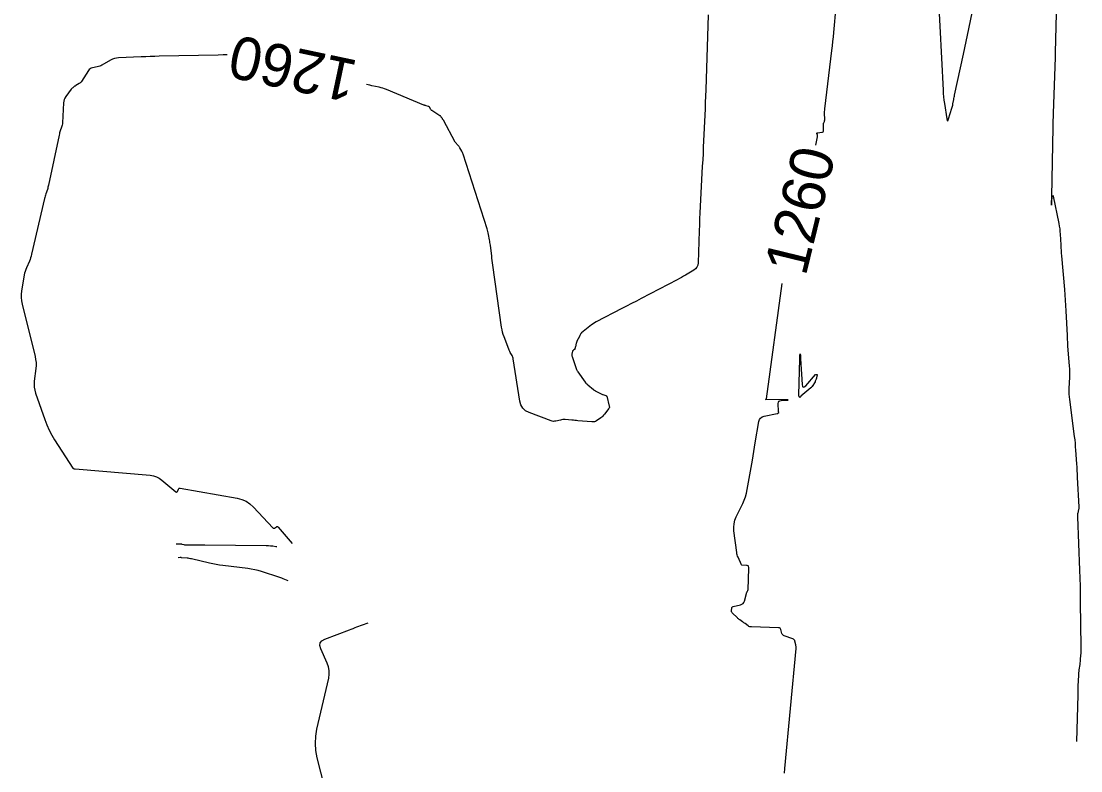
# Model space of a CAD drawing. Extents: x 658976 to 668726, y 639543 to 647196.
# Drawn here: x 660588.2 to 660736.7, y 642362.1 to 642467.2 of the extents above; entities that cross this region are included whole.
import ezdxf

# ---------------------------------------------------------------- set-up
doc = ezdxf.new("R2010")
doc.units = 0
doc.layers.add('Ex_Contour Labels', color=7, linetype='Continuous')
doc.layers.add('Ex_Major Contours', color=7, linetype='Continuous')

msp = doc.modelspace()

# ---------------------------------------------------------------- linework, layer by layer
at = {"layer": 'Ex_Major Contours'}
for points in [[(660733.36, 642471.99), (660733.11, 642462.8), (660733.11, 642462.62), (660733.1, 642462.44), (660733.1, 642462.27), (660733.09, 642462.09), (660732.81, 642454.31), (660732.8, 642453.8), (660732.78, 642453.29), (660732.77, 642452.78), (660732.76, 642452.27), (660732.59, 642442.62), (660732.58, 642442.53), (660732.58, 642442.45), (660732.58, 642442.36), (660732.58, 642442.27), (660732.57, 642441.44), (660732.57, 642441.41), (660732.57, 642441.4), (660732.57, 642441.41), (660732.57, 642441.44), (660732.59, 642441.75), (660732.59, 642441.77), (660732.59, 642441.8), (660732.59, 642441.83), (660732.59, 642441.86), (660732.6, 642441.98), (660732.61, 642442.01), (660732.61, 642442.04), (660732.61, 642442.07), (660732.62, 642442.1), (660732.73, 642442.64), (660732.76, 642442.72), (660732.78, 642442.74), (660732.8, 642442.72), (660732.82, 642442.64), (660733.61, 642438.84), (660733.68, 642438.47), (660733.74, 642438.09), (660733.78, 642437.72), (660733.81, 642437.34), (660733.88, 642435.81), (660733.9, 642435.43), (660733.93, 642435.05), (660733.96, 642434.67), (660733.99, 642434.29), (660734.41, 642429.55), (660734.47, 642428.81), (660734.52, 642428.06), (660734.57, 642427.32), (660734.61, 642426.58), (660734.77, 642423.13), (660734.79, 642422.62), (660734.82, 642422.11), (660734.85, 642421.6), (660734.89, 642421.09), (660735.07, 642418.82), (660735.09, 642418.43), (660735.11, 642418.04), (660735.11, 642417.65), (660735.09, 642417.25), (660735.02, 642415.68), (660735.01, 642415.29), (660735.02, 642414.9), (660735.05, 642414.51), (660735.09, 642414.12), (660735.78, 642408.96), (660735.84, 642408.48), (660735.89, 642408), (660735.93, 642407.52), (660735.97, 642407.04), (660736.1, 642405.12), (660736.13, 642404.64), (660736.16, 642404.16), (660736.19, 642403.67), (660736.21, 642403.19), (660736.41, 642399.07), (660736.42, 642398.98), (660736.41, 642398.88), (660736.4, 642398.79), (660736.38, 642398.69), (660736.26, 642398.21), (660736.25, 642398.17), (660736.24, 642398.12), (660736.23, 642398.08), (660736.23, 642398.03), (660736.24, 642397.84), (660736.24, 642397.8), (660736.24, 642397.75), (660736.24, 642397.7), (660736.24, 642397.66), (660736.53, 642390.18), (660736.56, 642389.06), (660736.6, 642387.95), (660736.62, 642386.83), (660736.63, 642385.72), (660736.7, 642379.44), (660736.7, 642379.23), (660736.69, 642379.03), (660736.69, 642378.82), (660736.68, 642378.61), (660736.63, 642377.77), (660736.62, 642377.57), (660736.6, 642377.38), (660736.58, 642377.18), (660736.55, 642376.99), (660736.44, 642376.21), (660736.41, 642376.01), (660736.39, 642375.82), (660736.38, 642375.62), (660736.37, 642375.43), (660736.3, 642373.97), (660736.29, 642373.66), (660736.28, 642373.35), (660736.27, 642373.04), (660736.26, 642372.73), (660736.11, 642366.16)], [(660716.72, 642471.05), (660717.39, 642457.52), (660717.42, 642457.06), (660717.46, 642456.59), (660717.51, 642456.13), (660717.57, 642455.67), (660717.9, 642453.52), (660717.95, 642453.29), (660718.01, 642453.21), (660718.09, 642453.28), (660718.17, 642453.5), (660718.62, 642454.98), (660718.66, 642455.13), (660718.7, 642455.29), (660718.74, 642455.44), (660718.77, 642455.59), (660718.88, 642456.21), (660718.91, 642456.36), (660718.94, 642456.52), (660718.97, 642456.67), (660719, 642456.83), (660720.24, 642462.59), (660720.43, 642463.47), (660720.62, 642464.35), (660720.81, 642465.23), (660720.99, 642466.11), (660722.04, 642471.11)], [(660699.55, 642449.82), (660699.77, 642450.96), (660699.78, 642451.02), (660699.78, 642451.08), (660699.78, 642451.14), (660699.77, 642451.2), (660699.71, 642451.43), (660699.71, 642451.49), (660699.72, 642451.52), (660699.76, 642451.55), (660699.81, 642451.56), (660700.39, 642451.62), (660700.49, 642451.64), (660700.57, 642451.69), (660700.61, 642451.77), (660700.62, 642451.88), (660700.61, 642452.71), (660700.61, 642452.76), (660700.62, 642452.82), (660700.64, 642452.88), (660700.66, 642452.93), (660700.76, 642453.14), (660700.78, 642453.19), (660700.79, 642453.25), (660700.8, 642453.3), (660700.8, 642453.36), (660700.77, 642454.33), (660700.77, 642454.38), (660700.77, 642454.43), (660700.77, 642454.47), (660700.78, 642454.52), (660700.8, 642454.71), (660700.8, 642454.76), (660700.81, 642454.8), (660700.81, 642454.85), (660700.82, 642454.9), (660701.81, 642463.08), (660701.88, 642463.72), (660701.95, 642464.36), (660702.02, 642465), (660702.08, 642465.63), (660702.42, 642469.26)], [(660684.46, 642468.07), (660684.12, 642457.59), (660684.09, 642456.7), (660684.06, 642455.8), (660684.02, 642454.91), (660683.98, 642454.01), (660683.82, 642450.43), (660683.78, 642449.54), (660683.74, 642448.65), (660683.69, 642447.75), (660683.64, 642446.86), (660683.34, 642441.19), (660683.29, 642440.33), (660683.25, 642439.48), (660683.22, 642438.62), (660683.19, 642437.77), (660683.04, 642433.3), (660683, 642432.98), (660682.88, 642432.71), (660682.7, 642432.48), (660682.45, 642432.28), (660681.3, 642431.59), (660681.01, 642431.42), (660680.72, 642431.25), (660680.43, 642431.09), (660680.13, 642430.93), (660675.06, 642428.29), (660674.39, 642427.94), (660673.71, 642427.59), (660673.03, 642427.24), (660672.36, 642426.88), (660668.77, 642425.01), (660668.54, 642424.89), (660668.32, 642424.75), (660668.1, 642424.6), (660667.89, 642424.44), (660666.7, 642423.47), (660666.69, 642423.46), (660666.67, 642423.45), (660666.66, 642423.44), (660666.65, 642423.42), (660666.6, 642423.36), (660666.59, 642423.35), (660666.58, 642423.33), (660666.57, 642423.32), (660666.56, 642423.3), (660666.48, 642423.13), (660666.46, 642423.09), (660666.45, 642423.06), (660666.43, 642423.03), (660666.41, 642422.99), (660666.07, 642422.34), (660666.06, 642422.32), (660666.05, 642422.3), (660666.04, 642422.27), (660666.03, 642422.25), (660666, 642422.15), (660665.99, 642422.12), (660665.98, 642422.1), (660665.98, 642422.07), (660665.97, 642422.05), (660665.84, 642421.52), (660665.83, 642421.49), (660665.82, 642421.46), (660665.81, 642421.43), (660665.8, 642421.4), (660665.76, 642421.23), (660665.75, 642421.23), (660665.75, 642421.22), (660665.75, 642421.21), (660665.75, 642421.2), (660665.75, 642421.18), (660665.75, 642421.17), (660665.75, 642421.16), (660665.74, 642421.16), (660665.74, 642421.15), (660665.56, 642421.06), (660665.55, 642421.06), (660665.54, 642421.05), (660665.52, 642421.04), (660665.51, 642421.02), (660665.48, 642420.97), (660665.47, 642420.96), (660665.46, 642420.95), (660665.45, 642420.93), (660665.45, 642420.92), (660665.35, 642420.49), (660665.34, 642420.41), (660665.34, 642420.34), (660665.35, 642420.26), (660665.37, 642420.19), (660666.01, 642418.35), (660666.05, 642418.26), (660666.09, 642418.17), (660666.13, 642418.09), (660666.19, 642418.01), (660667.21, 642416.56), (660667.24, 642416.53), (660667.27, 642416.49), (660667.3, 642416.46), (660667.33, 642416.43), (660667.46, 642416.32), (660667.49, 642416.29), (660667.52, 642416.26), (660667.56, 642416.23), (660667.59, 642416.2), (660668.37, 642415.52), (660668.39, 642415.51), (660668.41, 642415.49), (660668.43, 642415.48), (660668.46, 642415.46), (660668.55, 642415.41), (660668.57, 642415.4), (660668.6, 642415.38), (660668.62, 642415.37), (660668.64, 642415.36), (660669.66, 642414.83), (660669.67, 642414.83), (660669.68, 642414.82), (660669.69, 642414.82), (660669.7, 642414.82), (660670.09, 642414.72), (660670.14, 642414.7), (660670.18, 642414.67), (660670.21, 642414.63), (660670.23, 642414.58), (660670.6, 642413.19), (660670.62, 642413.11), (660670.61, 642413.03), (660670.59, 642412.96), (660670.54, 642412.89), (660669.91, 642412.06), (660669.8, 642411.92), (660669.67, 642411.8), (660669.54, 642411.68), (660669.4, 642411.57), (660668.82, 642411.16), (660668.67, 642411.07), (660668.51, 642411.01), (660668.35, 642410.98), (660668.17, 642410.99), (660666.21, 642411.16), (660665.99, 642411.18), (660665.78, 642411.2), (660665.57, 642411.22), (660665.35, 642411.24), (660664.41, 642411.31), (660664.24, 642411.32), (660664.08, 642411.31), (660663.91, 642411.29), (660663.75, 642411.26), (660663.09, 642411.1), (660662.93, 642411.08), (660662.77, 642411.07), (660662.61, 642411.1), (660662.45, 642411.14), (660659.37, 642412.3), (660658.86, 642412.56), (660658.47, 642412.92), (660658.2, 642413.37), (660658.05, 642413.92), (660657.12, 642419.83), (660657.1, 642419.95), (660657.06, 642420.07), (660657.02, 642420.19), (660656.96, 642420.3), (660656.72, 642420.74), (660656.66, 642420.85), (660656.6, 642420.96), (660656.55, 642421.07), (660656.51, 642421.19), (660655.85, 642422.91), (660655.73, 642423.24), (660655.64, 642423.58), (660655.56, 642423.92), (660655.5, 642424.26), (660654.28, 642432.99), (660654.23, 642433.31), (660654.19, 642433.63), (660654.15, 642433.94), (660654.11, 642434.26), (660653.93, 642435.78), (660653.9, 642435.97), (660653.87, 642436.16), (660653.84, 642436.35), (660653.81, 642436.54), (660653.66, 642437.3), (660653.62, 642437.49), (660653.58, 642437.68), (660653.53, 642437.87), (660653.47, 642438.05), (660650.11, 642448.54), (660650.07, 642448.65), (660650.02, 642448.76), (660649.98, 642448.87), (660649.92, 642448.97), (660649.66, 642449.44), (660649.62, 642449.51), (660649.57, 642449.58), (660649.52, 642449.65), (660649.46, 642449.72), (660649.22, 642449.97), (660649.16, 642450.03), (660649.11, 642450.1), (660649.06, 642450.17), (660649.01, 642450.24), (660647.34, 642453.3), (660647.3, 642453.36), (660647.27, 642453.41), (660647.23, 642453.47), (660647.2, 642453.53), (660647.05, 642453.75), (660647.01, 642453.8), (660646.97, 642453.85), (660646.92, 642453.9), (660646.86, 642453.93), (660645.72, 642454.65), (660645.67, 642454.69), (660645.62, 642454.74), (660645.58, 642454.79), (660645.55, 642454.85), (660645.44, 642455.09), (660645.41, 642455.15), (660645.37, 642455.19), (660645.32, 642455.23), (660645.25, 642455.25), (660644.91, 642455.34), (660644.83, 642455.36), (660644.76, 642455.39), (660644.68, 642455.41), (660644.6, 642455.44), (660639.35, 642457.6), (660639.1, 642457.69), (660638.85, 642457.78), (660638.6, 642457.85), (660638.34, 642457.92), (660637.3, 642458.15), (660637.04, 642458.21), (660636.79, 642458.27), (660636.58, 642458.33)], [(660617.01, 642462.47), (660616.46, 642462.46), (660615.76, 642462.44), (660607.5, 642462.27), (660606.87, 642462.25), (660606.24, 642462.24), (660605.61, 642462.21), (660604.98, 642462.19), (660601.79, 642462.05), (660601.5, 642462.02), (660601.22, 642461.96), (660600.95, 642461.86), (660600.69, 642461.73), (660599.47, 642461.02), (660599.32, 642460.94), (660599.16, 642460.87), (660598.99, 642460.82), (660598.82, 642460.78), (660598.13, 642460.64), (660597.97, 642460.6), (660597.82, 642460.52), (660597.7, 642460.41), (660597.59, 642460.28), (660596.62, 642458.75), (660596.55, 642458.66), (660596.47, 642458.58), (660596.39, 642458.5), (660596.29, 642458.44), (660595.82, 642458.18), (660595.76, 642458.14), (660595.7, 642458.1), (660595.64, 642458.06), (660595.59, 642458.02), (660595.37, 642457.85), (660595.32, 642457.8), (660595.27, 642457.75), (660595.22, 642457.7), (660595.18, 642457.65), (660594.4, 642456.62), (660594.27, 642456.42), (660594.18, 642456.22), (660594.12, 642456), (660594.09, 642455.76), (660593.94, 642452.92), (660593.93, 642452.78), (660593.9, 642452.63), (660593.87, 642452.49), (660593.82, 642452.35), (660593.62, 642451.8), (660593.58, 642451.66), (660593.53, 642451.52), (660593.5, 642451.38), (660593.46, 642451.23), (660591.99, 642444.22), (660591.95, 642444.06), (660591.91, 642443.9), (660591.87, 642443.74), (660591.82, 642443.58), (660591.6, 642442.96), (660591.55, 642442.8), (660591.5, 642442.64), (660591.46, 642442.48), (660591.42, 642442.32), (660589.62, 642434.5), (660589.56, 642434.26), (660589.48, 642434.01), (660589.4, 642433.77), (660589.3, 642433.53), (660588.88, 642432.59), (660588.79, 642432.35), (660588.71, 642432.11), (660588.64, 642431.86), (660588.59, 642431.61), (660588.21, 642429.35), (660588.16, 642428.89), (660588.15, 642428.43), (660588.19, 642427.98), (660588.28, 642427.52), (660590.1, 642420.19), (660590.18, 642419.76), (660590.23, 642419.33), (660590.23, 642418.9), (660590.2, 642418.47), (660589.99, 642416.73), (660589.96, 642416.29), (660589.98, 642415.87), (660590.05, 642415.45), (660590.17, 642415.03), (660591.45, 642411.31), (660591.73, 642410.57), (660592.06, 642409.85), (660592.43, 642409.15), (660592.84, 642408.47), (660595.4, 642404.51), (660595.42, 642404.48), (660595.44, 642404.47), (660595.46, 642404.45), (660595.49, 642404.44), (660595.59, 642404.42), (660595.62, 642404.41), (660595.65, 642404.4), (660595.68, 642404.4), (660595.7, 642404.4), (660606.23, 642403.5), (660606.68, 642403.43), (660607.1, 642403.29), (660607.49, 642403.1), (660607.86, 642402.83), (660609.85, 642401.19), (660609.92, 642401.15), (660609.97, 642401.15), (660610.02, 642401.18), (660610.06, 642401.24), (660610.21, 642401.57), (660610.25, 642401.64), (660610.31, 642401.69), (660610.38, 642401.71), (660610.46, 642401.71), (660618.42, 642400.29), (660619.07, 642400.13), (660619.67, 642399.86), (660620.22, 642399.5), (660620.72, 642399.05), (660623.43, 642396.15), (660623.49, 642396.1), (660623.55, 642396.08), (660623.61, 642396.09), (660623.68, 642396.11), (660623.95, 642396.27), (660624.01, 642396.3), (660624.07, 642396.3), (660624.13, 642396.28), (660624.18, 642396.23), (660626.13, 642393.94)], [(660695.15, 642361.74), (660695.19, 642362.36), (660696.78, 642379.21), (660696.79, 642379.34), (660696.78, 642379.47), (660696.77, 642379.59), (660696.75, 642379.72), (660696.63, 642380.22), (660696.59, 642380.34), (660696.53, 642380.43), (660696.44, 642380.5), (660696.33, 642380.56), (660695.12, 642380.97), (660695, 642381.03), (660694.91, 642381.11), (660694.84, 642381.21), (660694.79, 642381.33), (660694.66, 642381.86), (660694.61, 642381.98), (660694.54, 642382.06), (660694.44, 642382.11), (660694.32, 642382.13), (660690.54, 642382.23), (660690.41, 642382.24), (660690.29, 642382.27), (660690.18, 642382.32), (660690.07, 642382.39), (660689.63, 642382.7), (660689.53, 642382.76), (660689.44, 642382.83), (660689.35, 642382.9), (660689.26, 642382.96), (660688.89, 642383.23), (660688.8, 642383.3), (660688.71, 642383.37), (660688.63, 642383.44), (660688.55, 642383.52), (660687.82, 642384.23), (660687.77, 642384.3), (660687.73, 642384.37), (660687.72, 642384.44), (660687.72, 642384.52), (660687.77, 642384.87), (660687.79, 642384.94), (660687.83, 642385), (660687.88, 642385.05), (660687.96, 642385.08), (660689.01, 642385.34), (660689.2, 642385.41), (660689.35, 642385.52), (660689.46, 642385.66), (660689.53, 642385.85), (660689.9, 642387.13), (660689.91, 642387.16), (660689.92, 642387.19), (660689.93, 642387.21), (660689.95, 642387.24), (660690.02, 642387.33), (660690.03, 642387.35), (660690.04, 642387.38), (660690.05, 642387.41), (660690.05, 642387.44), (660690.15, 642390.47), (660690.15, 642390.49), (660690.15, 642390.51), (660690.15, 642390.55), (660690.15, 642390.55), (660690.15, 642390.56), (660690.15, 642390.57), (660690.15, 642390.58), (660690.1, 642390.77), (660690.1, 642390.77), (660690.1, 642390.78), (660690.09, 642390.78), (660690.09, 642390.78), (660690.06, 642390.79), (660690.05, 642390.79), (660690.05, 642390.79), (660690.04, 642390.79), (660690.03, 642390.8), (660689.91, 642390.84), (660689.89, 642390.85), (660689.86, 642390.85), (660689.84, 642390.86), (660689.82, 642390.86), (660689.18, 642390.92), (660689.17, 642390.92), (660689.15, 642390.93), (660689.14, 642390.94), (660689.13, 642390.95), (660688.65, 642392.01), (660688.59, 642392.17), (660688.54, 642392.34), (660688.49, 642392.51), (660688.47, 642392.68), (660688.07, 642395.71), (660688.04, 642396.22), (660688.08, 642396.72), (660688.2, 642397.2), (660688.39, 642397.68), (660689.31, 642399.55), (660689.52, 642400.02), (660689.7, 642400.5), (660689.84, 642401), (660689.94, 642401.51), (660690.66, 642405.65), (660690.76, 642406.25), (660690.86, 642406.85), (660690.96, 642407.45), (660691.06, 642408.05), (660691.55, 642411.03), (660691.64, 642411.31), (660691.79, 642411.53), (660692.01, 642411.69), (660692.29, 642411.79), (660694.13, 642412.15), (660694.16, 642412.15), (660694.18, 642412.16), (660694.21, 642412.18), (660694.23, 642412.2), (660694.35, 642412.31), (660694.36, 642412.32), (660694.37, 642412.32), (660694.37, 642412.33), (660694.36, 642412.35), (660694.34, 642412.39), (660694.34, 642412.4), (660694.34, 642412.41), (660694.33, 642412.43), (660694.33, 642412.44), (660694.29, 642413.58), (660694.31, 642413.75), (660694.38, 642413.88), (660694.5, 642413.96), (660694.67, 642413.99), (660695.48, 642414.05), (660695.63, 642414.06), (660695.68, 642414.07), (660695.63, 642414.08), (660695.48, 642414.08), (660692.52, 642414.12), (660692.5, 642414.12), (660692.5, 642414.12), (660692.5, 642414.13), (660692.51, 642414.14), (660692.58, 642414.17), (660692.6, 642414.18), (660692.61, 642414.19), (660692.62, 642414.21), (660692.62, 642414.22), (660694.81, 642430.39)], [(660609.87, 642393.89), (660610.39, 642393.9), (660610.46, 642393.9), (660610.53, 642393.89), (660610.61, 642393.88), (660610.68, 642393.86), (660610.96, 642393.78), (660611.03, 642393.76), (660611.11, 642393.75), (660611.18, 642393.74), (660611.25, 642393.74), (660612.78, 642393.77), (660613.05, 642393.77), (660613.33, 642393.77), (660613.61, 642393.77), (660613.89, 642393.77), (660622.49, 642393.64), (660622.57, 642393.64), (660622.64, 642393.64), (660622.72, 642393.64), (660622.8, 642393.64), (660623.11, 642393.62), (660623.19, 642393.62), (660623.27, 642393.61), (660623.34, 642393.61), (660623.42, 642393.6), (660623.86, 642393.53), (660623.87, 642393.53), (660623.89, 642393.53), (660623.9, 642393.53), (660623.91, 642393.53), (660623.98, 642393.53)], [(660625.59, 642388.69), (660624.9, 642388.99), (660624.79, 642389.04), (660624.67, 642389.08), (660624.55, 642389.12), (660624.43, 642389.16), (660621.84, 642390), (660621.37, 642390.14), (660620.89, 642390.26), (660620.4, 642390.36), (660619.91, 642390.43), (660616.43, 642390.85), (660615.95, 642390.91), (660615.48, 642390.99), (660615, 642391.08), (660614.54, 642391.18), (660612.02, 642391.78), (660611.87, 642391.81), (660611.72, 642391.84), (660611.58, 642391.86), (660611.43, 642391.88), (660610.63, 642391.95), (660610.58, 642391.96), (660610.54, 642391.96), (660610.49, 642391.96), (660610.45, 642391.96), (660610.18, 642391.94)], [(660630.67, 642359.86), (660629.66, 642363.88), (660629.47, 642364.89), (660629.4, 642365.89), (660629.45, 642366.9), (660629.62, 642367.91), (660631.27, 642375.06), (660631.35, 642375.6), (660631.34, 642376.12), (660631.25, 642376.64), (660631.06, 642377.14), (660630.14, 642379.15), (660630, 642379.61), (660630.05, 642380), (660630.29, 642380.31), (660630.71, 642380.54), (660634.16, 642381.84), (660634.42, 642381.94), (660634.69, 642382.04), (660634.95, 642382.14), (660635.22, 642382.24), (660636.81, 642382.83)]]:
    msp.add_lwpolyline(points, dxfattribs=at)
msp.add_lwpolyline([(660699.71, 642417.64), (660699.72, 642417.64), (660699.73, 642417.62), (660699.73, 642417.6), (660699.66, 642417.18), (660699.65, 642417.12), (660699.64, 642417.07), (660699.62, 642417.02), (660699.6, 642416.97), (660699.48, 642416.7), (660699.48, 642416.68), (660699.47, 642416.67), (660699.46, 642416.64), (660699.45, 642416.63), (660699.45, 642416.62), (660699.45, 642416.62), (660699.44, 642416.61), (660699.02, 642415.96), (660699.01, 642415.94), (660699, 642415.92), (660698.98, 642415.9), (660698.97, 642415.89), (660698.92, 642415.82), (660698.91, 642415.8), (660698.9, 642415.79), (660698.88, 642415.77), (660698.86, 642415.76), (660697.45, 642414.58), (660697.44, 642414.56), (660697.43, 642414.55), (660697.42, 642414.53), (660697.41, 642414.52), (660697.37, 642414.43), (660697.36, 642414.42), (660697.35, 642414.42), (660697.34, 642414.42), (660697.33, 642414.42), (660697.29, 642414.45), (660697.27, 642414.45), (660697.26, 642414.46), (660697.26, 642414.47), (660697.25, 642414.49), (660697.18, 642414.62), (660697.17, 642414.65), (660697.16, 642414.68), (660697.15, 642414.71), (660697.15, 642414.74), (660697.3, 642419.82), (660697.32, 642420.36), (660697.35, 642420.54), (660697.39, 642420.36), (660697.42, 642419.82), (660697.63, 642416.24), (660697.67, 642415.97), (660697.77, 642415.85), (660697.92, 642415.89), (660698.13, 642416.07), (660699.49, 642417.66), (660699.5, 642417.66), (660699.5, 642417.66), (660699.51, 642417.66), (660699.51, 642417.66), (660699.53, 642417.63), (660699.53, 642417.63), (660699.54, 642417.62), (660699.55, 642417.62), (660699.55, 642417.62), (660699.69, 642417.64)], close=True, dxfattribs=at)

# ---------------------------------------------------------------- texts
at = {"layer": 'Ex_Contour Labels'}
for rotation, p in [(168.0357, (660635.57, 642461.61)), (76.2777, (660698.12, 642431.3))]:
    msp.add_text('1260', height=6, rotation=rotation, dxfattribs=at).set_placement(p)

doc.saveas('drawing.dxf')
